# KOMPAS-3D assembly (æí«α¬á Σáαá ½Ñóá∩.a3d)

Referenced files in D:\МОДЕЛЬ ТАНКА Т90\СБОРКИ\сборка фара правая\: ограждение2.m3d, фара левая.m3d
Referenced files in D:\МОДЕЛЬ ТАНКА Т90\ДЕТАЛИ\ОБЩИЕ ДЕТАЛИ\: болт м1.m3d
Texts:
  Сборка фара левая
